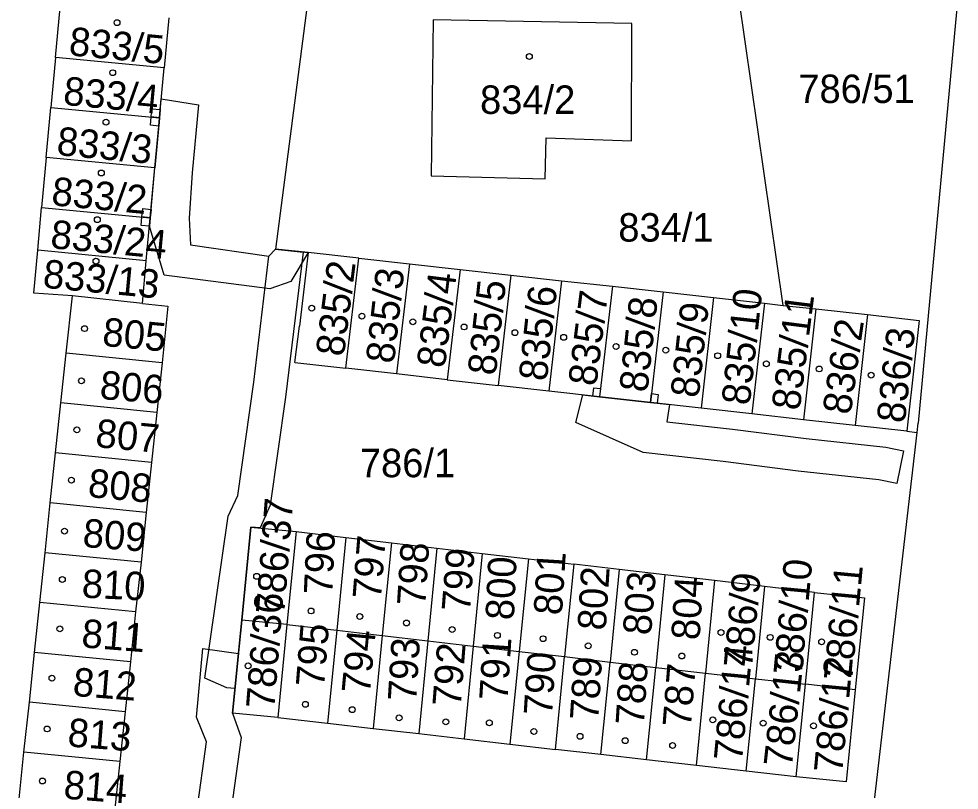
# Model space of a CAD drawing. Extents: x -755819 to -753140, y -1169796 to -1166000.
# Drawn here: x -755331.5 to -755275.4, y -1167320.5 to -1167274.4 of the extents above; entities that cross this region are included whole.
import ezdxf

# ---------------------------------------------------------------- set-up
doc = ezdxf.new("R2010")
doc.units = 0
for name, color, linetype in [('Vrstva 1', 7, 'Continuous'), ('Vrstva 18', 7, 'Continuous'), ('Vrstva 19', 7, 'Continuous'), ('Vrstva 25', 7, 'Continuous'), ('Vrstva 27', 7, 'Continuous'), ('Vrstva 6', 7, 'Continuous')]:
    doc.layers.add(name, color=color, linetype=linetype)

msp = doc.modelspace()

# ---------------------------------------------------------------- linework, layer by layer
at = {"layer": 'Vrstva 1'}
for p, q in [((-755285.88, -1167291.51), (-755289.3, -1167267.64)), ((-755275.36, -1167272.33), (-755277.82, -1167298.55)), ((-755329.34, -1167276.7), (-755329.06, -1167273.72)), ((-755322.58, -1167274.33), (-755322.86, -1167277.31)), ((-755306.78, -1167274.45), (-755306.91, -1167283.77)), ((-755294.92, -1167274.66), (-755306.78, -1167274.45)), ((-755294.93, -1167281.67), (-755294.92, -1167274.66)), ((-755329.34, -1167276.7), (-755329.62, -1167279.69)), ((-755322.86, -1167277.31), (-755329.34, -1167276.7)), ((-755323.14, -1167280.3), (-755322.86, -1167277.31)), ((-755329.9, -1167282.67), (-755329.62, -1167279.69)), ((-755329.62, -1167279.69), (-755323.14, -1167280.3)), ((-755323.14, -1167280.3), (-755323.41, -1167283.29)), ((-755300.09, -1167283.94), (-755300.04, -1167281.49)), ((-755300.04, -1167281.49), (-755294.93, -1167281.67)), ((-755329.9, -1167282.67), (-755330.18, -1167285.66)), ((-755323.41, -1167283.29), (-755329.9, -1167282.67)), ((-755323.69, -1167286.28), (-755323.41, -1167283.29)), ((-755306.91, -1167283.77), (-755300.09, -1167283.94)), ((-755330.41, -1167288.22), (-755330.18, -1167285.66)), ((-755330.18, -1167285.66), (-755323.69, -1167286.28)), ((-755323.93, -1167288.84), (-755323.69, -1167286.28)), ((-755330.65, -1167290.78), (-755330.41, -1167288.22)), ((-755323.93, -1167288.84), (-755330.41, -1167288.22)), ((-755314.25, -1167288.36), (-755316.21, -1167288.15)), ((-755314.25, -1167288.36), (-755314.77, -1167292.76)), ((-755311.23, -1167288.69), (-755314.25, -1167288.36)), ((-755324.16, -1167291.4), (-755323.93, -1167288.84)), ((-755312.01, -1167295.27), (-755311.23, -1167288.69)), ((-755311.23, -1167288.69), (-755308.2, -1167289.03)), ((-755308.2, -1167289.03), (-755308.97, -1167295.61)), ((-755308.2, -1167289.03), (-755305.17, -1167289.36)), ((-755305.17, -1167289.36), (-755305.94, -1167295.95)), ((-755305.17, -1167289.36), (-755302.14, -1167289.7)), ((-755302.14, -1167289.7), (-755302.91, -1167296.29)), ((-755302.14, -1167289.7), (-755299.11, -1167290.04)), ((-755299.11, -1167290.04), (-755299.88, -1167296.63)), ((-755299.11, -1167290.04), (-755296.08, -1167290.37)), ((-755296.08, -1167290.37), (-755296.84, -1167296.97)), ((-755296.08, -1167290.37), (-755293.05, -1167290.71)), ((-755328.33, -1167290.95), (-755330.65, -1167290.78)), ((-755328.72, -1167294.36), (-755328.33, -1167290.95)), ((-755324.16, -1167291.4), (-755328.33, -1167290.95)), ((-755293.05, -1167290.71), (-755293.81, -1167297.31)), ((-755293.05, -1167290.71), (-755290.03, -1167291.05)), ((-755290.03, -1167291.05), (-755290.78, -1167297.65)), ((-755290.03, -1167291.05), (-755287, -1167291.38)), ((-755324.16, -1167291.4), (-755322.64, -1167291.55)), ((-755322.64, -1167291.55), (-755322.98, -1167294.94)), ((-755287, -1167291.38), (-755287.74, -1167297.99)), ((-755287, -1167291.38), (-755285.88, -1167291.51)), ((-755285.88, -1167291.51), (-755283.92, -1167291.72)), ((-755283.92, -1167291.72), (-755284.66, -1167298.34)), ((-755283.92, -1167291.72), (-755280.84, -1167292.06)), ((-755280.84, -1167292.06), (-755281.58, -1167298.68)), ((-755280.84, -1167292.06), (-755277.75, -1167292.41)), ((-755315.04, -1167294.93), (-755314.77, -1167292.76)), ((-755277.75, -1167292.41), (-755278.43, -1167298.47)), ((-755329.03, -1167297.34), (-755328.72, -1167294.36)), ((-755322.98, -1167294.94), (-755328.72, -1167294.36)), ((-755322.98, -1167294.94), (-755323.3, -1167297.92)), ((-755315.04, -1167294.93), (-755312.01, -1167295.27)), ((-755308.97, -1167295.61), (-755312.01, -1167295.27)), ((-755305.94, -1167295.95), (-755308.97, -1167295.61)), ((-755305.94, -1167295.95), (-755302.91, -1167296.29)), ((-755299.88, -1167296.63), (-755302.91, -1167296.29)), ((-755296.84, -1167296.97), (-755299.88, -1167296.63)), ((-755329.35, -1167300.32), (-755329.03, -1167297.34)), ((-755323.3, -1167297.92), (-755329.03, -1167297.34)), ((-755293.81, -1167297.31), (-755296.84, -1167296.97)), ((-755290.78, -1167297.65), (-755293.81, -1167297.31)), ((-755323.3, -1167297.92), (-755323.61, -1167300.9)), ((-755287.74, -1167297.99), (-755290.78, -1167297.65)), ((-755284.66, -1167298.34), (-755287.74, -1167297.99)), ((-755281.58, -1167298.68), (-755284.66, -1167298.34)), ((-755278.43, -1167298.47), (-755278.49, -1167299.03)), ((-755278.49, -1167299.03), (-755281.58, -1167298.68)), ((-755278.49, -1167299.03), (-755277.88, -1167299.1)), ((-755277.88, -1167299.1), (-755277.82, -1167298.55)), ((-755283.5, -1167347.72), (-755277.88, -1167299.1)), ((-755329.66, -1167303.31), (-755329.35, -1167300.32)), ((-755323.61, -1167300.9), (-755329.35, -1167300.32)), ((-755323.61, -1167300.9), (-755323.93, -1167303.88)), ((-755329.97, -1167306.29), (-755329.66, -1167303.31)), ((-755323.93, -1167303.88), (-755329.66, -1167303.31)), ((-755323.93, -1167303.88), (-755324.24, -1167306.86)), ((-755318.22, -1167310.32), (-755317.67, -1167304.76)), ((-755317.67, -1167304.76), (-755314.98, -1167305.03)), ((-755314.98, -1167305.03), (-755315.53, -1167310.58)), ((-755314.98, -1167305.03), (-755312, -1167305.38)), ((-755312, -1167305.38), (-755312.55, -1167310.92)), ((-755312, -1167305.38), (-755309.28, -1167305.7)), ((-755309.28, -1167305.7), (-755309.83, -1167311.24)), ((-755309.28, -1167305.7), (-755306.56, -1167306.02)), ((-755330.29, -1167309.27), (-755329.97, -1167306.29)), ((-755324.24, -1167306.86), (-755329.97, -1167306.29)), ((-755306.56, -1167306.02), (-755307.11, -1167311.56)), ((-755306.56, -1167306.02), (-755303.85, -1167306.33)), ((-755303.85, -1167306.33), (-755304.39, -1167311.87)), ((-755303.85, -1167306.33), (-755301.1, -1167306.66)), ((-755324.24, -1167306.86), (-755324.56, -1167309.83)), ((-755301.1, -1167306.66), (-755301.65, -1167312.19)), ((-755301.1, -1167306.66), (-755298.39, -1167306.97)), ((-755298.39, -1167306.97), (-755298.93, -1167312.5)), ((-755295.67, -1167307.29), (-755298.39, -1167306.97)), ((-755295.67, -1167307.29), (-755296.21, -1167312.82)), ((-755292.95, -1167307.61), (-755295.67, -1167307.29)), ((-755292.95, -1167307.61), (-755293.49, -1167313.14)), ((-755289.97, -1167307.96), (-755292.95, -1167307.61)), ((-755289.97, -1167307.96), (-755290.52, -1167313.48)), ((-755286.99, -1167308.31), (-755289.97, -1167307.96)), ((-755286.99, -1167308.31), (-755287.53, -1167313.82)), ((-755284, -1167308.66), (-755286.99, -1167308.31)), ((-755284.55, -1167314.15), (-755284, -1167308.66)), ((-755284, -1167308.66), (-755281.02, -1167308.98)), ((-755281.02, -1167308.98), (-755281.57, -1167314.49)), ((-755330.6, -1167312.25), (-755330.29, -1167309.27)), ((-755324.56, -1167309.83), (-755330.29, -1167309.27)), ((-755324.56, -1167309.83), (-755324.87, -1167312.81)), ((-755318.78, -1167315.88), (-755318.22, -1167310.32)), ((-755315.53, -1167310.58), (-755318.22, -1167310.32)), ((-755315.53, -1167310.58), (-755316.07, -1167316.14)), ((-755315.53, -1167310.58), (-755312.55, -1167310.92)), ((-755312.55, -1167310.92), (-755313.09, -1167316.48)), ((-755312.55, -1167310.92), (-755309.83, -1167311.24)), ((-755309.83, -1167311.24), (-755310.37, -1167316.79)), ((-755309.83, -1167311.24), (-755307.11, -1167311.56)), ((-755307.11, -1167311.56), (-755307.65, -1167317.1)), ((-755307.11, -1167311.56), (-755304.39, -1167311.87)), ((-755304.39, -1167311.87), (-755304.94, -1167317.42)), ((-755304.39, -1167311.87), (-755301.65, -1167312.19)), ((-755330.91, -1167315.23), (-755330.6, -1167312.25)), ((-755324.87, -1167312.81), (-755330.6, -1167312.25)), ((-755301.65, -1167312.19), (-755302.2, -1167317.73)), ((-755301.65, -1167312.19), (-755298.93, -1167312.5)), ((-755299.48, -1167318.04), (-755298.93, -1167312.5)), ((-755298.93, -1167312.5), (-755296.21, -1167312.82)), ((-755324.87, -1167312.81), (-755325.19, -1167315.79)), ((-755296.76, -1167318.35), (-755296.21, -1167312.82)), ((-755296.21, -1167312.82), (-755293.49, -1167313.14)), ((-755294.04, -1167318.66), (-755293.49, -1167313.14)), ((-755293.49, -1167313.14), (-755290.52, -1167313.48)), ((-755291.06, -1167319), (-755290.52, -1167313.48)), ((-755290.52, -1167313.48), (-755287.53, -1167313.82)), ((-755288.08, -1167319.34), (-755287.53, -1167313.82)), ((-755287.53, -1167313.82), (-755284.55, -1167314.15)), ((-755285.1, -1167319.68), (-755284.55, -1167314.15)), ((-755281.57, -1167314.49), (-755284.55, -1167314.15)), ((-755281.57, -1167314.49), (-755282.12, -1167319.99)), ((-755331.23, -1167318.21), (-755330.91, -1167315.23)), ((-755325.19, -1167315.79), (-755330.91, -1167315.23)), ((-755325.19, -1167315.79), (-755325.5, -1167318.77)), ((-755316.07, -1167316.14), (-755318.78, -1167315.88)), ((-755316.07, -1167316.14), (-755313.09, -1167316.48)), ((-755313.09, -1167316.48), (-755310.37, -1167316.79)), ((-755310.37, -1167316.79), (-755307.65, -1167317.1)), ((-755307.65, -1167317.1), (-755304.94, -1167317.42)), ((-755304.94, -1167317.42), (-755302.2, -1167317.73)), ((-755302.2, -1167317.73), (-755299.48, -1167318.04)), ((-755296.76, -1167318.35), (-755299.48, -1167318.04)), ((-755331.54, -1167321.19), (-755331.23, -1167318.21)), ((-755325.5, -1167318.77), (-755331.23, -1167318.21)), ((-755294.04, -1167318.66), (-755296.76, -1167318.35)), ((-755291.06, -1167319), (-755294.04, -1167318.66)), ((-755325.5, -1167318.77), (-755325.82, -1167321.75)), ((-755288.08, -1167319.34), (-755291.06, -1167319)), ((-755285.1, -1167319.68), (-755288.08, -1167319.34)), ((-755282.12, -1167319.99), (-755285.1, -1167319.68))]:
    msp.add_line(p, q, dxfattribs=at)
at = {"layer": 'Vrstva 25'}
for centre in [(-755325.67, -1167274.62), (-755301.04, -1167276.64), (-755325.93, -1167277.61), (-755326.33, -1167280.56), (-755326.61, -1167283.6), (-755326.85, -1167286.39), (-755326.93, -1167288.87), (-755314.04, -1167291.68), (-755311.04, -1167292.15), (-755327.61, -1167292.9), (-755308, -1167292.49), (-755304.94, -1167292.8), (-755301.9, -1167293.14), (-755298.99, -1167293.42), (-755295.86, -1167293.97), (-755292.89, -1167294.19), (-755289.79, -1167294.52), (-755286.88, -1167295), (-755283.72, -1167295.31), (-755280.62, -1167295.68), (-755327.8, -1167296.02), (-755328.07, -1167298.95), (-755328.4, -1167301.95), (-755328.81, -1167305), (-755328.94, -1167307.89), (-755317.33, -1167307.7), (-755314.08, -1167309.77), (-755311.17, -1167310.1), (-755329.09, -1167310.84), (-755308.38, -1167310.49), (-755305.65, -1167310.88), (-755302.95, -1167311.23), (-755300.22, -1167311.43), (-755289.59, -1167311.06), (-755286.65, -1167311.35), (-755297.52, -1167311.85), (-755283.58, -1167311.61), (-755294.76, -1167312.24), (-755291.93, -1167312.46), (-755317.84, -1167313.05), (-755329.56, -1167313.79), (-755314.42, -1167315.35), (-755311.62, -1167315.67), (-755308.82, -1167316.16), (-755306.03, -1167316.4), (-755303.43, -1167316.45), (-755290.08, -1167316.28), (-755287.07, -1167316.47), (-755284.06, -1167316.63), (-755329.85, -1167316.82), (-755300.77, -1167316.97), (-755298.01, -1167317.26), (-755295.31, -1167317.52), (-755292.48, -1167317.81), (-755330.13, -1167319.93)]:
    msp.add_circle(centre, 0.175, dxfattribs=at)
at = {"layer": 'Vrstva 27'}
for p, q in [((-755323.09, -1167279.8), (-755323.03, -1167279.16)), ((-755323.03, -1167279.16), (-755320.81, -1167279.52)), ((-755323.64, -1167280.25), (-755323.59, -1167279.76)), ((-755323.59, -1167279.76), (-755323.09, -1167279.8)), ((-755323.14, -1167280.3), (-755323.09, -1167279.8)), ((-755323.09, -1167279.8), (-755323.14, -1167280.3)), ((-755320.81, -1167279.52), (-755321.18, -1167283.6)), ((-755323.68, -1167280.75), (-755323.64, -1167280.25)), ((-755323.14, -1167280.3), (-755323.64, -1167280.25)), ((-755323.64, -1167280.25), (-755323.14, -1167280.3)), ((-755323.18, -1167280.8), (-755323.14, -1167280.3)), ((-755323.14, -1167280.3), (-755323.18, -1167280.8)), ((-755323.18, -1167280.8), (-755323.68, -1167280.75)), ((-755323.41, -1167283.29), (-755323.18, -1167280.8)), ((-755323.64, -1167285.78), (-755323.41, -1167283.29)), ((-755321.18, -1167283.6), (-755321.36, -1167286.29)), ((-755324.19, -1167286.23), (-755324.14, -1167285.73)), ((-755324.14, -1167285.73), (-755323.64, -1167285.78)), ((-755323.69, -1167286.28), (-755323.64, -1167285.78)), ((-755323.64, -1167285.78), (-755323.69, -1167286.28)), ((-755324.23, -1167286.73), (-755324.19, -1167286.23)), ((-755323.69, -1167286.28), (-755324.19, -1167286.23)), ((-755324.19, -1167286.23), (-755323.69, -1167286.28)), ((-755323.74, -1167286.78), (-755323.69, -1167286.28)), ((-755323.69, -1167286.28), (-755323.74, -1167286.78)), ((-755321.36, -1167286.29), (-755321.29, -1167287.89)), ((-755323.74, -1167286.78), (-755324.23, -1167286.73)), ((-755322.86, -1167289.7), (-755323.74, -1167286.78)), ((-755321.29, -1167287.89), (-755316.6, -1167288.58)), ((-755316.6, -1167288.58), (-755316.21, -1167288.15)), ((-755316.6, -1167288.58), (-755316.21, -1167288.15)), ((-755316.21, -1167288.15), (-755314.56, -1167288.33)), ((-755316.21, -1167288.15), (-755314.25, -1167288.36)), ((-755314.56, -1167288.33), (-755315.6, -1167296.99)), ((-755314.25, -1167288.36), (-755315.28, -1167290.09)), ((-755317.5, -1167296.09), (-755316.6, -1167288.58)), ((-755316.55, -1167290.53), (-755322.86, -1167289.7)), ((-755315.28, -1167290.09), (-755316.55, -1167290.53)), ((-755318.46, -1167302.87), (-755317.5, -1167296.09)), ((-755297.24, -1167296.93), (-755297.18, -1167296.43)), ((-755297.18, -1167296.43), (-755296.78, -1167296.47)), ((-755296.78, -1167296.47), (-755296.84, -1167296.97)), ((-755293.81, -1167297.31), (-755293.75, -1167296.78)), ((-755293.75, -1167296.78), (-755293.34, -1167296.84)), ((-755315.6, -1167296.99), (-755316.52, -1167303.45)), ((-755298.27, -1167298.5), (-755297.85, -1167296.86)), ((-755297.85, -1167296.86), (-755296.84, -1167296.97)), ((-755296.84, -1167296.97), (-755297.24, -1167296.93)), ((-755296.84, -1167296.97), (-755293.81, -1167297.31)), ((-755293.81, -1167297.31), (-755293.41, -1167297.36)), ((-755293.41, -1167297.36), (-755293.81, -1167297.31)), ((-755293.34, -1167296.84), (-755293.41, -1167297.36)), ((-755293.41, -1167297.36), (-755292.67, -1167297.44)), ((-755292.67, -1167297.44), (-755292.82, -1167298.46)), ((-755292.82, -1167298.46), (-755288.91, -1167298.9)), ((-755294.23, -1167300.3), (-755298.27, -1167298.5)), ((-755288.91, -1167298.9), (-755284.5, -1167299.46)), ((-755284.5, -1167299.46), (-755279.74, -1167299.98)), ((-755279.74, -1167299.98), (-755278.68, -1167300.21)), ((-755289.47, -1167300.84), (-755294.23, -1167300.3)), ((-755278.68, -1167300.21), (-755279.09, -1167302.16)), ((-755284.98, -1167301.42), (-755289.47, -1167300.84)), ((-755280.16, -1167301.94), (-755284.98, -1167301.42)), ((-755279.09, -1167302.16), (-755280.16, -1167301.94)), ((-755319.03, -1167304.1), (-755318.46, -1167302.87)), ((-755316.52, -1167303.45), (-755317.13, -1167304.81)), ((-755320.42, -1167313.79), (-755319.03, -1167304.1)), ((-755317.67, -1167304.76), (-755318.22, -1167310.32)), ((-755317.13, -1167304.81), (-755317.67, -1167304.76)), ((-755318.22, -1167310.32), (-755318.63, -1167314.41)), ((-755320.92, -1167316.11), (-755320.55, -1167312.02)), ((-755320.55, -1167312.02), (-755318.42, -1167312.32)), ((-755318.42, -1167312.32), (-755318.78, -1167315.88)), ((-755319.11, -1167314.37), (-755320.42, -1167313.79)), ((-755318.63, -1167314.41), (-755319.11, -1167314.37)), ((-755318.78, -1167315.88), (-755318.26, -1167317.33)), ((-755320.32, -1167317.59), (-755320.92, -1167316.11)), ((-755321.17, -1167323.72), (-755320.32, -1167317.59)), ((-755318.26, -1167317.33), (-755319.25, -1167324.38))]:
    msp.add_line(p, q, dxfattribs=at)
at = {"layer": 'Vrstva 6'}
msp.add_line((-755313.48, -1167267.1), (-755316.21, -1167288.15), dxfattribs=at)

# ---------------------------------------------------------------- texts
at = {"layer": 'Vrstva 18'}
for s, p in [('786/51', (-755284.97, -1167279.42)), ('834/1', (-755295.723, -1167287.7)), ('786/1', (-755311.163, -1167301.78))]:
    msp.add_text(s, height=1.7, dxfattribs=at).set_placement(p)
at = {"layer": 'Vrstva 19'}
for s, rotation, p in [('833/5', 354.6036, (-755328.591, -1167276.56)), ('833/4', 354.6036, (-755328.931, -1167279.52)), ('833/3', 354.6036, (-755329.321, -1167282.52)), ('833/2', 354.6036, (-755329.631, -1167285.52)), ('833/24', 354.6036, (-755329.693, -1167288.086)), ('833/13', 354.6036, (-755330.145, -1167290.448)), ('835/2', 82.7924, (-755312.122, -1167294.608)), ('835/3', 83.7091, (-755309.126, -1167295.028)), ('835/4', 82.7924, (-755306.092, -1167295.298)), ('835/5', 83.7091, (-755303.046, -1167295.738)), ('835/6', 83.7091, (-755299.996, -1167296.078)), ('835/10', 83.7091, (-755287.877, -1167297.522)), ('835/7', 82.7924, (-755297.042, -1167296.378)), ('835/8', 83.7091, (-755293.986, -1167296.748)), ('835/11', 82.7924, (-755284.89, -1167297.834)), ('835/9', 83.7091, (-755290.926, -1167297.078)), ('805', 354.6036, (-755326.594, -1167293.922)), ('836/2', 81.8757, (-755281.848, -1167298.089)), ('836/3', 83.7091, (-755278.606, -1167298.588)), ('806', 355.5203, (-755326.743, -1167297.099)), ('807', 354.6036, (-755327.004, -1167299.972)), ('808', 354.6036, (-755327.454, -1167302.952)), ('786/37', 85.4853, (-755315.687, -1167310.023)), ('809', 355.5203, (-755327.763, -1167305.939)), ('796', 87.3188, (-755312.819, -1167308.823)), ('797', 85.4853, (-755309.911, -1167309.113)), ('798', 86.402, (-755307.255, -1167309.503)), ('799', 85.4853, (-755304.591, -1167309.863)), ('800', 87.3188, (-755301.969, -1167310.343)), ('801', 86.402, (-755299.095, -1167310.053)), ('786/10', 84.6259, (-755284.773, -1167313.669)), ('810', 357.2965, (-755327.803, -1167308.971)), ('802', 86.402, (-755296.475, -1167310.963)), ('786/11', 84.6259, (-755281.762, -1167314.005)), ('803', 85.4853, (-755293.771, -1167311.253)), ('804', 86.402, (-755290.875, -1167311.543)), ('786/9', 84.6259, (-755287.742, -1167313.225)), ('786/36', 85.4853, (-755316.277, -1167315.663)), ('811', 355.5203, (-755327.833, -1167311.939)), ('795', 85.4853, (-755313.301, -1167314.363)), ('794', 84.6259, (-755310.568, -1167314.754)), ('793', 86.402, (-755307.805, -1167315.213)), ('792', 85.4853, (-755305.141, -1167315.533)), ('791', 86.402, (-755302.345, -1167315.173)), ('786/14', 84.6259, (-755288.333, -1167318.789)), ('790', 86.402, (-755299.685, -1167316.053)), ('786/13', 83.7091, (-755285.362, -1167319.153)), ('789', 86.402, (-755296.925, -1167316.343)), ('788', 86.402, (-755294.195, -1167316.633)), ('787', 85.4853, (-755291.391, -1167316.763)), ('786/12', 84.6259, (-755282.353, -1167319.499)), ('812', 355.5203, (-755328.353, -1167314.839)), ('813', 355.5203, (-755328.663, -1167317.859)), ('814', 355.5203, (-755328.903, -1167320.979))]:
    msp.add_text(s, height=1.7, rotation=rotation, dxfattribs=at).set_placement(p)
msp.add_text('834/2', height=1.7, dxfattribs=at).set_placement((-755303.983, -1167280.07))

doc.saveas('drawing.dxf')
